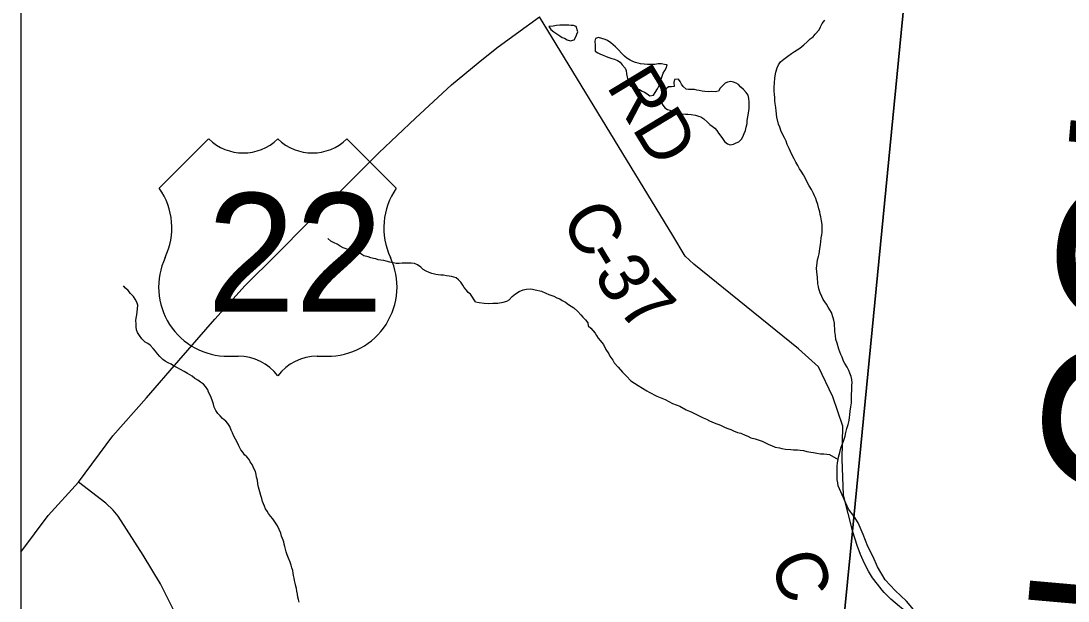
# Model space of a CAD drawing. Extents: x 0 to 34, y 0 to 22.
# Drawn here: x 17.162 to 18.328, y 19.518 to 20.164 of the extents above; entities that cross this region are included whole.
import ezdxf

# ---------------------------------------------------------------- set-up
doc = ezdxf.new("R2010")
doc.units = 0
for name, color, linetype in [('GM_X_Corporation', 7, 'Continuous'), ('GM_X_County_Road', 7, 'Continuous'), ('GM_X_County_Road_Text', 7, 'Continuous'), ('GM_X_County_Text', 7, 'Continuous'), ('GM_X_Minor_Lake', 7, 'Continuous'), ('GM_X_Minor_River', 7, 'Continuous'), ('GM_X_State_Route', 7, 'Continuous'), ('GM_X_Township_Road', 7, 'Continuous'), ('GM_X_US_Location', 7, 'Continuous'), ('GM_X_US_Route', 7, 'Continuous'), ('GM_X_US_Shield', 7, 'Continuous')]:
    doc.layers.add(name, color=color, linetype=linetype)

msp = doc.modelspace()

# ---------------------------------------------------------------- linework, layer by layer
at = {"layer": 'GM_X_Corporation'}
for points in [[(18.23, 21.1059), (17.1625, 21.1059), (17.1625, 14.3059), (17.597, 14.3059), (17.6136, 14.4601), (17.7239, 15.6245), (17.7373, 15.7617), (17.7834, 16.317), (17.8718, 17.2256), (17.9672, 18.2605), (18.0387, 19.0962), (18.0879, 19.5959), (18.1731, 20.4696), (18.203, 20.7746)], [(18.23, 21.1059), (17.1625, 21.1059), (17.1625, 16.0215), (17.412, 16.1394), (17.7834, 16.317), (17.8718, 17.2256), (17.9672, 18.2605), (18.0387, 19.0962), (18.0879, 19.5959), (18.1731, 20.4696), (18.203, 20.7746)], [(17.597, 14.3059), (23.9625, 14.3059), (23.9625, 21.1059), (18.23, 21.1059), (18.203, 20.7746), (18.1731, 20.4696), (18.0879, 19.5959), (18.0387, 19.0962), (17.9672, 18.2605), (17.8718, 17.2256), (17.7834, 16.317), (17.7373, 15.7617), (17.7239, 15.6245), (17.6136, 14.4601)]]:
    msp.add_lwpolyline(points, close=True, dxfattribs=at)
msp.add_lwpolyline([(22.4736, 19.0897), (21.6862, 19.7442), (21.462, 19.9289), (21.2024, 20.1483), (21.1503, 20.1924), (20.9887, 20.3291), (20.5209, 20.5272), (20.0591, 20.7271), (19.4417, 20.9771), (19.1325, 21.1059), (18.23, 21.1059), (18.203, 20.7746), (18.1731, 20.4696), (18.0879, 19.5959), (18.0387, 19.0962), (17.9672, 18.2605), (17.8718, 17.2256), (17.7834, 16.317)], dxfattribs=at)
at = {"layer": 'GM_X_County_Road'}
for points in [[(18.0881, 19.5954), (18.0777, 19.6361), (18.0764, 19.676), (18.077, 19.7128), (18.0661, 19.7456), (18.05, 19.7789), (18.0279, 19.7989), (17.9112, 19.8929), (17.9015, 19.9018), (17.8878, 19.9248), (17.7394, 20.168)], [(18.2364, 19.392), (18.2257, 19.4095), (18.2165, 19.4241), (18.2048, 19.4425), (18.1978, 19.4533), (18.1895, 19.4649), (18.1822, 19.4741), (18.174, 19.4834), (18.1675, 19.49), (18.1601, 19.4965), (18.1479, 19.5062), (18.144, 19.5092), (18.1401, 19.5123), (18.1307, 19.5204), (18.1249, 19.5261), (18.1233, 19.5279), (18.121, 19.5305), (18.1156, 19.5371), (18.1103, 19.5441), (18.1056, 19.5515), (18.1013, 19.5599), (18.0968, 19.5702), (18.0931, 19.5801), (18.0881, 19.5954)]]:
    msp.add_lwpolyline(points, dxfattribs=at)
at = {"layer": 'GM_X_Minor_Lake'}
for p, q in [((17.8816, 20.1148), (17.8786, 20.1149)), ((17.8943, 20.0987), (17.8898, 20.0984))]:
    msp.add_line(p, q, dxfattribs=at)
for points in [[(17.7806, 20.1476), (17.7811, 20.1489), (17.7823, 20.1515), (17.7805, 20.1573), (17.7775, 20.1584), (17.7748, 20.1585), (17.7721, 20.1589), (17.7683, 20.1589), (17.7653, 20.159), (17.7623, 20.1587), (17.7585, 20.1583), (17.7547, 20.1576), (17.7499, 20.1572)], [(17.7499, 20.1572), (17.7523, 20.1539), (17.7557, 20.1515), (17.7587, 20.1492), (17.7621, 20.1469), (17.7647, 20.1453), (17.7674, 20.1442), (17.7704, 20.1426), (17.7742, 20.1414), (17.778, 20.1425), (17.7799, 20.1459), (17.7806, 20.1476)], [(17.8786, 20.1149), (17.8752, 20.1157), (17.8718, 20.1157), (17.868, 20.115), (17.8649, 20.1151), (17.8623, 20.1151), (17.8596, 20.1151), (17.8562, 20.1156), (17.852, 20.116), (17.8494, 20.1164), (17.8464, 20.1172), (17.8433, 20.1184), (17.8403, 20.12), (17.8369, 20.1223), (17.8343, 20.1242), (17.8309, 20.1277), (17.8279, 20.1312), (17.8242, 20.1346), (17.8216, 20.1369), (17.8189, 20.1393), (17.8152, 20.1416), (17.8125, 20.1428), (17.8091, 20.1439), (17.8054, 20.1451), (17.8019, 20.144), (17.8011, 20.141), (17.8014, 20.1365), (17.8017, 20.13), (17.8044, 20.1281), (17.8074, 20.1265), (17.8104, 20.1253), (17.8138, 20.1241), (17.8168, 20.123), (17.8202, 20.1218), (17.8232, 20.121), (17.8263, 20.1194), (17.8293, 20.1178), (17.8315, 20.1148), (17.8349, 20.1109), (17.836, 20.1083), (17.8363, 20.1048), (17.837, 20.101), (17.8377, 20.098), (17.8388, 20.0945), (17.8407, 20.0911), (17.8444, 20.0895), (17.8478, 20.088), (17.8509, 20.0872), (17.8539, 20.0856), (17.8565, 20.0844), (17.8595, 20.0825), (17.8625, 20.0802), (17.8663, 20.0809), (17.8683, 20.0839), (17.871, 20.088), (17.8726, 20.0918), (17.8734, 20.0944), (17.8746, 20.0978), (17.8757, 20.1009), (17.8773, 20.1054), (17.8789, 20.1084), (17.8804, 20.111), (17.8816, 20.1148)], [(17.8898, 20.0984), (17.8889, 20.095), (17.8893, 20.0908), (17.8866, 20.0901), (17.8832, 20.0901), (17.8805, 20.0879), (17.8786, 20.0849), (17.8766, 20.0815), (17.8758, 20.0788), (17.8754, 20.075), (17.8761, 20.0709), (17.8791, 20.067), (17.8821, 20.0651), (17.8847, 20.0643), (17.8874, 20.0627), (17.8908, 20.0615), (17.8949, 20.0603), (17.898, 20.0603), (17.9021, 20.0599), (17.9048, 20.0598), (17.9082, 20.0594), (17.9131, 20.0586), (17.9165, 20.0578), (17.9192, 20.057), (17.9226, 20.0546), (17.9267, 20.0508), (17.9293, 20.0485), (17.9319, 20.0465), (17.9346, 20.0442), (17.9368, 20.0415), (17.9387, 20.0388), (17.9424, 20.0339), (17.9454, 20.0296), (17.9487, 20.0269), (17.9518, 20.0258), (17.9556, 20.0265), (17.9586, 20.0279), (17.9613, 20.029), (17.9644, 20.032), (17.9659, 20.0347), (17.9675, 20.0384), (17.9687, 20.0415), (17.9695, 20.0452), (17.9707, 20.0494), (17.9708, 20.0528), (17.972, 20.0608), (17.9728, 20.0661), (17.9729, 20.0687), (17.9729, 20.0737), (17.9726, 20.0771), (17.9719, 20.0809), (17.9697, 20.084), (17.9667, 20.0871), (17.9637, 20.0898), (17.9611, 20.0928), (17.9584, 20.0944), (17.9554, 20.0956), (17.9524, 20.096), (17.9489, 20.0953), (17.9463, 20.0942), (17.9432, 20.0912), (17.9405, 20.0886), (17.9386, 20.0856), (17.9351, 20.0848), (17.9313, 20.0849), (17.9275, 20.0846), (17.9237, 20.085), (17.9207, 20.0854), (17.9173, 20.0862), (17.9147, 20.0866), (17.912, 20.0871), (17.909, 20.0871), (17.9055, 20.0872), (17.9029, 20.0876), (17.8995, 20.0907), (17.8977, 20.0933), (17.8962, 20.096), (17.8943, 20.0987)]]:
    msp.add_lwpolyline(points, dxfattribs=at)
at = {"layer": 'GM_X_Minor_River'}
for points in [[(18.0174, 20.0218), (18.0152, 20.026), (18.0141, 20.0298), (18.0122, 20.0336), (18.0085, 20.0405), (18.0071, 20.0455), (18.0056, 20.0489), (18.0038, 20.0565), (18.0028, 20.0634), (18.0025, 20.0672), (18.0018, 20.0718), (18.0014, 20.0748), (18.0015, 20.0782), (18.0012, 20.0816), (18.0008, 20.0854), (18.0009, 20.09), (18.001, 20.0942), (18.0014, 20.1002), (18.0027, 20.1067), (18.0039, 20.1112), (18.0054, 20.1146), (18.0077, 20.118), (18.0116, 20.121), (18.0158, 20.1243), (18.02, 20.1273), (18.0235, 20.1295), (18.0262, 20.1314), (18.0292, 20.1333), (18.0338, 20.137), (18.0373, 20.1404), (18.0408, 20.1437), (18.0442, 20.146), (18.0465, 20.149), (18.0508, 20.1535), (18.0523, 20.1569), (18.0543, 20.1606), (18.057, 20.1644)], [(18.0835, 19.6205), (18.0721, 19.6463), (18.0714, 19.6497), (18.071, 19.6531), (18.0707, 19.6569), (18.0708, 19.6611), (18.0708, 19.6657), (18.0709, 19.6683), (18.0713, 19.6721), (18.0721, 19.6759), (18.0725, 19.6785), (18.0737, 19.6835), (18.0745, 19.6869), (18.0753, 19.6895), (18.0769, 19.6933), (18.0781, 19.6974), (18.0797, 19.7016), (18.0805, 19.7058), (18.0817, 19.7103), (18.0829, 19.7148), (18.0841, 19.719), (18.0845, 19.7224), (18.085, 19.7254), (18.0854, 19.7296), (18.0862, 19.7342), (18.0867, 19.7387), (18.0867, 19.7417), (18.0868, 19.7455), (18.0868, 19.749), (18.0872, 19.7516), (18.0873, 19.755), (18.0873, 19.7584), (18.0874, 19.7611), (18.087, 19.7649), (18.0863, 19.768), (18.0849, 19.7718), (18.0838, 19.7748), (18.0819, 19.7786), (18.0793, 19.7825), (18.0778, 19.7852), (18.0764, 19.7894), (18.0749, 19.7924), (18.0727, 19.7985), (18.0709, 19.805), (18.0694, 19.8092), (18.0691, 19.8138), (18.0684, 19.8183), (18.0681, 19.821), (18.0678, 19.8248), (18.0678, 19.8274), (18.0671, 19.8309), (18.0664, 19.8335), (18.0645, 19.8393), (18.0608, 19.845), (18.059, 19.8485), (18.0553, 19.8538), (18.0538, 19.8569), (18.0519, 19.8611), (18.0505, 19.8657), (18.0502, 19.8683), (18.0494, 19.871), (18.0488, 19.8786), (18.0484, 19.8813), (18.0481, 19.8843), (18.0478, 19.8885), (18.0482, 19.8911), (18.0486, 19.8945), (18.0491, 19.898), (18.0502, 19.9017), (18.0507, 19.9044), (18.0515, 19.9101), (18.0523, 19.915), (18.0528, 19.918), (18.0532, 19.9222), (18.0536, 19.9256), (18.054, 19.9286), (18.0541, 19.9336), (18.0542, 19.937), (18.0535, 19.9412), (18.0528, 19.9457), (18.052, 19.9484), (18.0517, 19.9511), (18.0506, 19.9545), (18.0492, 19.9595), (18.0477, 19.9633), (18.047, 19.9659), (18.0455, 19.969), (18.0444, 19.9717), (18.0422, 19.9759), (18.0396, 19.9801), (18.037, 19.9851), (18.0352, 19.9889), (18.0333, 19.9923), (18.0307, 19.9965), (18.0288, 19.9992), (18.027, 20.0027), (18.0248, 20.0065), (18.0229, 20.0103), (18.0211, 20.0134), (18.0189, 20.0184), (18.0174, 20.0218)], [(17.6683, 19.851), (17.6628, 19.8595), (17.6602, 19.8615), (17.6584, 19.8642), (17.6558, 19.8669), (17.6543, 19.8696), (17.6521, 19.873), (17.6495, 19.8754), (17.6469, 19.8777), (17.6442, 19.8785), (17.6416, 19.8793), (17.6389, 19.8798), (17.6362, 19.8802), (17.6328, 19.8806), (17.6298, 19.8807), (17.6267, 19.8811), (17.6241, 19.8816), (17.6199, 19.8828), (17.6169, 19.8836), (17.6135, 19.8852), (17.6101, 19.8871), (17.6075, 19.8895), (17.6037, 19.8922), (17.6003, 19.8938), (17.5969, 19.8942), (17.5935, 19.8943), (17.59, 19.8943), (17.5866, 19.894), (17.5835, 19.8937), (17.5801, 19.8938), (17.5767, 19.8946), (17.5729, 19.8954), (17.5691, 19.8963), (17.5665, 19.8971), (17.563, 19.8975), (17.56, 19.8979), (17.5574, 19.8988), (17.5547, 19.8992), (17.5517, 19.9), (17.549, 19.9012), (17.5441, 19.9024), (17.5407, 19.9044), (17.5381, 19.9052), (17.5343, 19.9064), (17.5309, 19.9076), (17.5282, 19.9084), (17.5244, 19.91), (17.521, 19.9112), (17.5176, 19.9132), (17.5143, 19.9151), (17.5109, 19.9167), (17.5075, 19.9187), (17.5041, 19.9214)], [(17.3625, 19.7616), (17.3595, 19.7639), (17.3561, 19.7659), (17.3531, 19.7686), (17.3478, 19.7713), (17.3441, 19.7737), (17.3399, 19.776), (17.3358, 19.778), (17.3324, 19.78), (17.3298, 19.7816), (17.3264, 19.7831), (17.323, 19.7851), (17.3204, 19.7871), (17.317, 19.7902), (17.3144, 19.7933), (17.3122, 19.7963), (17.3096, 19.7991), (17.3062, 19.8029), (17.3036, 19.8049), (17.3006, 19.8064), (17.2969, 19.8099), (17.2943, 19.8138), (17.2921, 19.8169), (17.291, 19.8199), (17.2907, 19.8234), (17.2908, 19.8268), (17.2904, 19.8302), (17.2909, 19.8329), (17.2914, 19.8367), (17.2918, 19.8401), (17.2923, 19.8435), (17.2924, 19.8473), (17.2913, 19.8507), (17.2895, 19.8542), (17.2876, 19.8569), (17.2846, 19.8604), (17.2817, 19.8639), (17.2787, 19.8662), (17.2765, 19.8689)], [(17.6683, 19.851), (17.6725, 19.8505), (17.6781, 19.8496), (17.6823, 19.8492), (17.6876, 19.8495), (17.6933, 19.8498), (17.699, 19.8508), (17.7032, 19.8519), (17.7059, 19.8534), (17.709, 19.8572), (17.7128, 19.8601), (17.7171, 19.8627), (17.7213, 19.8646), (17.7251, 19.8653), (17.7293, 19.8656), (17.7319, 19.8652), (17.7349, 19.8644), (17.7417, 19.8628), (17.7467, 19.8608), (17.75, 19.8592), (17.7557, 19.8573), (17.7587, 19.8557), (17.7621, 19.8545), (17.7648, 19.8526), (17.7685, 19.8506), (17.7719, 19.8483), (17.7749, 19.8464), (17.7776, 19.8444), (17.7821, 19.8402), (17.7854, 19.8367), (17.7877, 19.834), (17.7907, 19.831), (17.7933, 19.8279), (17.7936, 19.8245), (17.7966, 19.8218), (17.8015, 19.8164), (17.8029, 19.8137), (17.8048, 19.8106), (17.8108, 19.8037), (17.8133, 19.798), (17.8167, 19.7934), (17.8178, 19.7907), (17.8212, 19.7861), (17.8226, 19.7834), (17.8271, 19.7784), (17.832, 19.773), (17.8365, 19.7684), (17.8413, 19.7634), (17.8492, 19.758), (17.859, 19.7522), (17.8617, 19.7506), (17.8703, 19.7463), (17.8794, 19.7424), (17.8877, 19.7381), (17.8956, 19.7349), (17.9028, 19.731), (17.9065, 19.7295), (17.9092, 19.7283), (17.9137, 19.726), (17.9164, 19.7248), (17.9216, 19.722), (17.9254, 19.7205), (17.9288, 19.7189), (17.9314, 19.7177), (17.9341, 19.7166), (17.9409, 19.7138), (17.9454, 19.7118), (17.948, 19.7107), (17.9526, 19.7091), (17.9556, 19.7075), (17.9598, 19.7059), (17.9635, 19.7051), (17.9684, 19.7028), (17.9715, 19.7016), (17.9749, 19.7), (17.9794, 19.6988), (17.9839, 19.6972), (17.9873, 19.6961), (17.9911, 19.6941), (17.9949, 19.6925), (17.9979, 19.6914), (18.002, 19.6894), (18.0066, 19.6886), (18.0092, 19.6878), (18.0134, 19.6873), (18.0191, 19.6869), (18.0221, 19.6865), (18.0267, 19.6864), (18.0297, 19.686), (18.0335, 19.6859), (18.0369, 19.6847), (18.0415, 19.6839), (18.0445, 19.6835), (18.0483, 19.6827), (18.0521, 19.6822), (18.0559, 19.6822), (18.0593, 19.6818), (18.0623, 19.6813), (18.0721, 19.6759)], [(17.4721, 19.5172), (17.4714, 19.5199), (17.4707, 19.5226), (17.4704, 19.526), (17.4697, 19.5294), (17.469, 19.5321), (17.4683, 19.5348), (17.4676, 19.5382), (17.4669, 19.5413), (17.4666, 19.5439), (17.4659, 19.5466), (17.4656, 19.5493), (17.4649, 19.5523), (17.4638, 19.5554), (17.4631, 19.5581), (17.4621, 19.5615), (17.4603, 19.5661), (17.4588, 19.5696), (17.4577, 19.573), (17.457, 19.5761), (17.4563, 19.5788), (17.4556, 19.5814), (17.4549, 19.5841), (17.4535, 19.5879), (17.4524, 19.5906), (17.4517, 19.5937), (17.4499, 19.5979), (17.4481, 19.6021), (17.4452, 19.6063), (17.4429, 19.6098), (17.4403, 19.6129), (17.4381, 19.6156), (17.4366, 19.6183), (17.4348, 19.621), (17.4337, 19.6237), (17.4326, 19.6264), (17.4312, 19.6291), (17.4305, 19.6325), (17.4294, 19.6356), (17.4284, 19.6398), (17.427, 19.6451), (17.4263, 19.6485), (17.4256, 19.6527), (17.4245, 19.6562), (17.4242, 19.6589), (17.4235, 19.6623), (17.4221, 19.665), (17.421, 19.6677), (17.4199, 19.6703), (17.4177, 19.673), (17.4166, 19.6757), (17.414, 19.6788), (17.4114, 19.6808), (17.4095, 19.6838), (17.4073, 19.6866), (17.4051, 19.6908), (17.4026, 19.6958), (17.4011, 19.6985), (17.3989, 19.7023), (17.3978, 19.7054), (17.3964, 19.7084), (17.3949, 19.7123), (17.3927, 19.7157), (17.3905, 19.7184), (17.3867, 19.7215), (17.3841, 19.7243), (17.3815, 19.727), (17.3793, 19.7304), (17.3775, 19.7339), (17.3768, 19.7373), (17.3757, 19.7408), (17.3743, 19.7446), (17.3732, 19.7473), (17.3714, 19.7507), (17.3703, 19.7534), (17.3677, 19.7569), (17.3655, 19.7596), (17.3625, 19.7616)], [(18.1778, 19.3772), (18.1786, 19.3827), (18.1812, 19.3955), (18.1849, 19.4095), (18.1877, 19.4201), (18.185, 19.4338), (18.1792, 19.4475), (18.1738, 19.4613), (18.1714, 19.4712), (18.1693, 19.4807), (18.1654, 19.4949), (18.1596, 19.5045), (18.1481, 19.518), (18.1354, 19.53), (18.1243, 19.542), (18.1159, 19.5565), (18.1108, 19.5676), (18.105, 19.5791), (18.0996, 19.5925), (18.0941, 19.6054), (18.0896, 19.6122), (18.0835, 19.6205)]]:
    msp.add_lwpolyline(points, dxfattribs=at)
at = {"layer": 'GM_X_State_Route'}
for points in [[(17.2266, 19.6507), (17.2649, 19.7019), (17.3021, 19.7444), (17.3381, 19.786), (17.3783, 19.8319), (17.412, 19.8694), (17.4468, 19.9039), (17.4816, 19.9388), (17.5206, 19.9767), (17.5608, 20.0168), (17.6017, 20.0554), (17.6418, 20.0925), (17.6715, 20.117), (17.692, 20.1335), (17.7139, 20.1497), (17.7394, 20.168)], [(17.1625, 19.5726), (17.1929, 19.6136), (17.2266, 19.6507)]]:
    msp.add_lwpolyline(points, dxfattribs=at)
at = {"layer": 'GM_X_Township_Road'}
msp.add_lwpolyline([(17.3895, 19.1543), (17.3909, 19.1756), (17.3979, 19.2325), (17.3998, 19.2464), (17.3998, 19.2523), (17.3998, 19.2632), (17.3989, 19.2771), (17.388, 19.3424), (17.3796, 19.3805), (17.3711, 19.4127), (17.3588, 19.4478), (17.3395, 19.4944), (17.3177, 19.5374), (17.2984, 19.5695), (17.2707, 19.6126), (17.2652, 19.6195), (17.2568, 19.627), (17.2266, 19.6507)], dxfattribs=at)
at = {"layer": 'GM_X_US_Route'}
for points in [[(17.2266, 19.6507), (17.2649, 19.7019), (17.3021, 19.7444), (17.3381, 19.786), (17.3783, 19.8319), (17.412, 19.8694), (17.4468, 19.9039), (17.4816, 19.9388), (17.5206, 19.9767), (17.5608, 20.0168), (17.6017, 20.0554), (17.6418, 20.0925), (17.6715, 20.117), (17.692, 20.1335), (17.7139, 20.1497), (17.7394, 20.168)], [(17.1625, 19.5726), (17.1929, 19.6136), (17.2266, 19.6507)]]:
    msp.add_lwpolyline(points, dxfattribs=at)
at = {"layer": 'GM_X_US_Shield'}
for p, q in [((17.3714, 20.0324), (17.3165, 19.9775)), ((17.5802, 19.9775), (17.5253, 20.0324)), ((17.3934, 19.7907), (17.4044, 19.7907)), ((17.4923, 19.7907), (17.5033, 19.7907))]:
    msp.add_line(p, q, dxfattribs=at)
for centre, radius, start, end in [((17.4099, 20.0716), 0.0549, 225.573, 314.427), ((17.4868, 20.0716), 0.0549, 225.573, 314.427), ((17.2535, 19.9334), 0.0769, 334.5471, 35.0009), ((17.6432, 19.9334), 0.0769, 144.9991, 205.4529), ((17.3926, 19.8676), 0.0769, 154.8319, 270.6383), ((17.5041, 19.8676), 0.0769, 269.3617, 25.1681), ((17.4044, 19.7358), 0.0549, 36.8699, 90), ((17.4923, 19.7358), 0.0549, 90, 143.1301)]:
    msp.add_arc(centre, radius, start, end, dxfattribs=at)

# ---------------------------------------------------------------- texts
at = {"layer": 'GM_X_County_Road_Text'}
for s, height, rotation, p in [('RD', 0.05682, 301.2192, (17.8133, 20.0913)), ('C', 0.0568, 301.0187, (17.762, 19.9424)), ('-', 0.0568, 301.2226, (17.7861, 19.9022)), ('3', 0.0568, 302.1036, (17.7987, 19.8814)), ('7', 0.0568, 313.3261, (17.8248, 19.8422)), ('C', 0.0568, 289.7959, (17.9953, 19.5634))]:
    msp.add_text(s, height=height, rotation=rotation, dxfattribs=at).set_placement(p)
at = {"layer": 'GM_X_County_Text'}
msp.add_text('CLINTON COUNTY', height=0.189394, rotation=84.9582, dxfattribs=at).set_placement((18.3783, 18.4377))
at = {"layer": 'GM_X_US_Location'}
for s in ['0', '/']:
    msp.add_text(s, height=0.000189, dxfattribs=at).set_placement((17.4483, 19.905))
msp.add_text('22', height=0.000189, rotation=0, dxfattribs=at).set_placement((17.4092, 19.8658))
at = {"layer": 'GM_X_US_Shield'}
msp.add_text('22', height=0.13184, dxfattribs=at).set_placement((17.3696, 19.8402))

doc.saveas('drawing.dxf')
